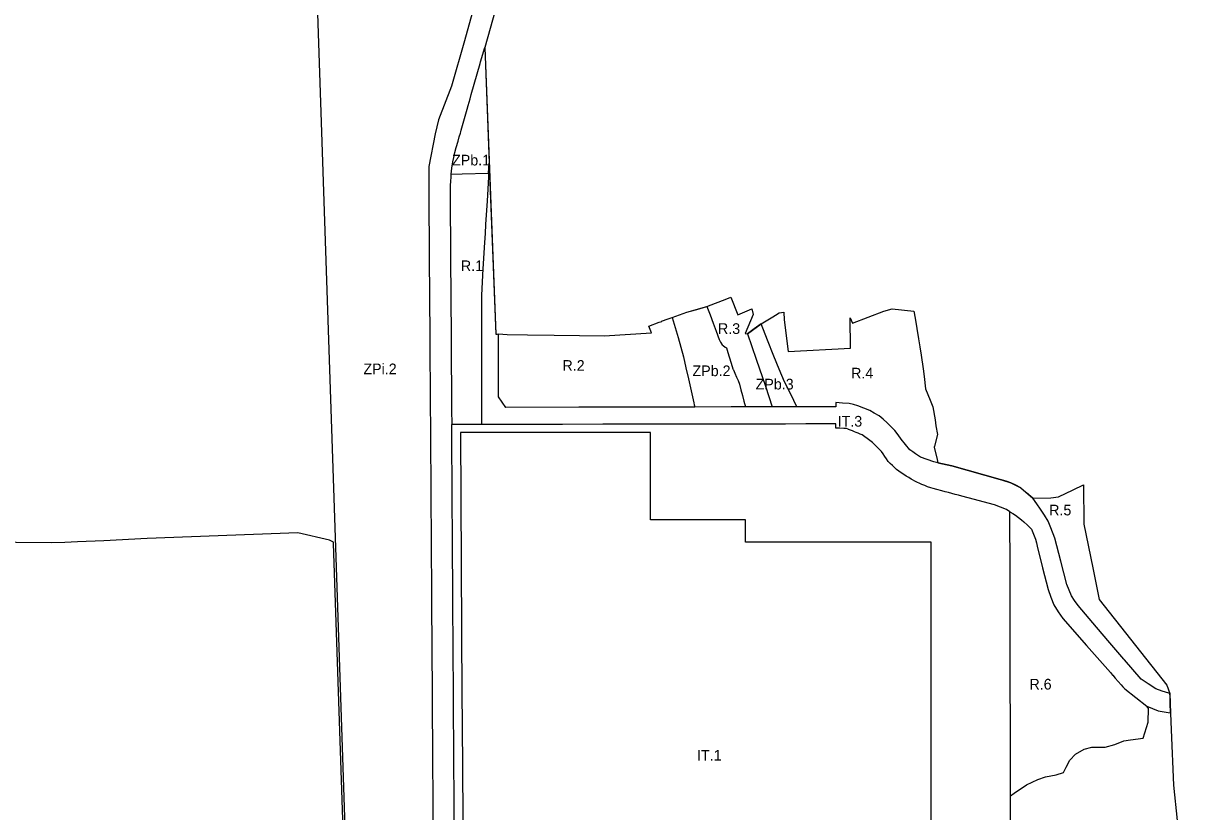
# Model space of a CAD drawing. Extents: x 7434685 to 7436459, y 5545868 to 5548111.
# Drawn here: x 7435281 to 7436385, y 5546598 to 5547337 of the extents above; entities that cross this region are included whole.
import ezdxf

# ---------------------------------------------------------------- set-up
doc = ezdxf.new("R2010")
doc.units = 0
for name, color, linetype in [('LIN_Granica Planu', 7, 'Continuous'), ('LIN_linia regulacyjna_1', 7, 'Continuous'), ('LIN_Linia Zabudowy Nieprzekraczalna', 7, 'Continuous'), ('LIN_Linie Rozgraniczajace', 7, 'Continuous'), ('TXT_Oznaczenia Przeznaczenia', 7, 'Continuous')]:
    doc.layers.add(name, color=color, linetype=linetype)

msp = doc.modelspace()

# ---------------------------------------------------------------- linework, layer by layer
at = {"layer": 'LIN_Granica Planu'}
msp.add_lwpolyline([(7435723.5, 5547350.6), (7435713.4, 5547315), (7435724, 5547046), (7435726.3, 5547046.4), (7435734.4, 5547045.9), (7435753.7, 5547045.4), (7435778.6, 5547045.2), (7435802.4, 5547044.8), (7435825.5, 5547044.4), (7435869.8, 5547047.2), (7435867.2, 5547053.5), (7435876.9, 5547057.4), (7435879.4, 5547058), (7435879.2, 5547058.3), (7435885.4, 5547060.4), (7435889.1, 5547061.8), (7435902.9, 5547066.6), (7435921.8, 5547071.9), (7435940.4, 5547079.3), (7435944.1, 5547080.8), (7435950.8, 5547064.1), (7435963.9, 5547069.8), (7435965.1, 5547064.5), (7435957.5, 5547046.7), (7435959.7, 5547046.3), (7435972.7, 5547055.9), (7435983.5, 5547062.4), (7435986.2, 5547064), (7435989.6, 5547066), (7435993.9, 5547066.8), (7435994.3, 5547059.6), (7435998, 5547029.9), (7436056.4, 5547032.9), (7436055.9, 5547061.5), (7436058.1, 5547056.3), (7436087.6, 5547067.6), (7436095.4, 5547069.9), (7436115.6, 5547067.7), (7436117, 5547061.2), (7436120.1, 5547041.6), (7436121.3, 5547034.2), (7436122.5, 5547026.3), (7436124.4, 5547013.6), (7436125.3, 5547006.3), (7436126.8, 5546994.7), (7436131, 5546984.1), (7436133.6, 5546977.8), (7436135.8, 5546965.8), (7436136.3, 5546960.2), (7436138, 5546952.1), (7436135.1, 5546941), (7436134.9, 5546940.2), (7436137.6, 5546928.4), (7436138.1, 5546925.5), (7436151.5, 5546922.6), (7436196.6, 5546909.9), (7436198, 5546909.5), (7436206.7, 5546906.7), (7436215.9, 5546902), (7436227.2, 5546892.3), (7436244.1, 5546892.7), (7436251.4, 5546893.4), (7436265.1, 5546900.2), (7436274.7, 5546904.8), (7436275.1, 5546867.9), (7436283.5, 5546826.8), (7436289.6, 5546797.3), (7436352.9, 5546717), (7436355.8, 5546709.1), (7436356.5, 5546690.7), (7436357.1, 5546675), (7436359.2, 5546623), (7436366, 5546556.9)], dxfattribs=at)
at = {"layer": 'LIN_linia regulacyjna_1'}
msp.add_lwpolyline([(7435243.6, 5546543.7), (7435297.9, 5546410.5), (7435304.7, 5546395.2), (7435312.3, 5546376.8), (7435316.9, 5546368.8), (7435318.9, 5546363), (7435321.5, 5546284.9), (7435321.5, 5546278.2), (7435590.7, 5546285.6), (7435571.7, 5546849.8), (7435571.7, 5546850.9), (7435567.9, 5546853), (7435538.3, 5546859.6), (7435397.1, 5546854.4), (7435356.3, 5546852.2), (7435331.6, 5546851.4), (7435319.9, 5546850.7), (7435306.9, 5546850.4), (7435208.7, 5546851.2)], dxfattribs=at)
at = {"layer": 'LIN_Linia Zabudowy Nieprzekraczalna'}
for p, q in [((7435868.8, 5546953.9), (7435766.5, 5546953.9)), ((7435868.8, 5546872.1), (7435868.8, 5546953.9)), ((7435914, 5546872.1), (7435868.8, 5546872.1))]:
    msp.add_line(p, q, dxfattribs=at)
for points in [[(7435766.5, 5546953.9), (7435690.6, 5546953.9), (7435692.1, 5546706.5), (7435692.3, 5546682.4), (7435692.6, 5546636), (7435692.7, 5546624), (7435692.8, 5546608.2), (7435693.9, 5546441.6), (7435693.9, 5546431.1), (7435693.9, 5546431.1), (7435694, 5546410.7), (7435694.2, 5546381.2), (7435694.9, 5546359.7), (7435695.6, 5546346.7), (7435695.4, 5546331.7), (7435695.7, 5546310.3), (7435684.1, 5546291.7), (7435651.3, 5546239), (7435648.5, 5546234.6), (7435646.4, 5546231.2), (7435623.7, 5546194.8)], [(7436132, 5546524.1), (7436132, 5546850.9), (7435957.9, 5546850.9), (7435957.9, 5546872.1), (7435914, 5546872.1)]]:
    msp.add_lwpolyline(points, dxfattribs=at)
at = {"layer": 'LIN_Linie Rozgraniczajace'}
msp.add_line((7435717.1, 5547197.1), (7435717.6, 5547206.5), dxfattribs=at)
for points in [[(7435729.9, 5547939.7), (7435729.9, 5547939.7), (7435729.9, 5547939.7), (7435732.1, 5547940.1), (7435745.6, 5547942.7), (7435761.3, 5547945.8), (7435757.5, 5547889.9), (7435754.2, 5547842.4), (7435754, 5547839.8), (7435745.7, 5547707.4), (7435745, 5547694.9), (7435742, 5547643), (7435737.4, 5547559.5), (7435734.9, 5547515.1), (7435730.9, 5547445.3), (7435730.9, 5547444.1), (7435730.9, 5547444.1), (7435730.9, 5547444.1), (7435730, 5547427.8), (7435726.4, 5547363.7), (7435726.2, 5547360), (7435723.5, 5547350.6), (7435713.4, 5547315)], [(7435592.7, 5546283.7), (7435573.9, 5546846), (7435555.2, 5547402.9)], [(7435701.8, 5547347.2), (7435694.4, 5547321.2), (7435682.3, 5547278.7), (7435670.2, 5547247), (7435667, 5547234.1), (7435660.9, 5547203.2), (7435661.1, 5547183.7), (7435661.2, 5547163.3), (7435661.2, 5547156.8), (7435661.2, 5547154.9), (7435661.3, 5547140.3), (7435661.4, 5547137.1), (7435661.4, 5547128.2), (7435661.5, 5547109.1), (7435661.7, 5547090.1), (7435661.8, 5547075.9), (7435661.8, 5547065.2), (7435661.9, 5547059.9), (7435661.9, 5547052.8), (7435661.9, 5547047.2), (7435662.1, 5547028.8), (7435662.1, 5547021.4), (7435662.2, 5547000.2), (7435662.4, 5546979.8), (7435662.4, 5546972.5), (7435662.5, 5546965.1), (7435662.6, 5546961.8), (7435662.6, 5546950.8), (7435662.7, 5546928.1), (7435662.8, 5546920), (7435662.8, 5546908.9), (7435662.9, 5546894.1), (7435663, 5546883.1), (7435663, 5546877), (7435663.1, 5546869.4), (7435663.2, 5546852.1), (7435663.2, 5546849.3), (7435663.2, 5546845.9), (7435663.3, 5546829.3), (7435663.4, 5546823.3), (7435663.4, 5546816.3), (7435663.4, 5546815.3), (7435663.5, 5546808.7), (7435663.5, 5546807.7), (7435663.6, 5546792.3), (7435663.7, 5546779.4), (7435663.8, 5546766.7), (7435663.9, 5546753.1), (7435663.9, 5546740.6), (7435664.1, 5546719.6), (7435664.1, 5546712.7), (7435664.1, 5546706.9), (7435664.2, 5546699.7), (7435664.2, 5546694.6), (7435664.2, 5546692.1), (7435664.2, 5546691.1), (7435664.3, 5546682.8), (7435664.4, 5546668.8), (7435664.5, 5546658.8), (7435664.5, 5546648.7), (7435664.6, 5546636.4), (7435664.6, 5546632.6), (7435664.7, 5546624.4), (7435664.8, 5546608.6), (7435665, 5546569.7)], [(7435681.9, 5547196), (7435682.6, 5547201.8), (7435683.6, 5547207.6), (7435684.4, 5547211.7), (7435685.4, 5547216.3), (7435686.8, 5547221.2), (7435688.5, 5547227.2), (7435689.6, 5547231.1), (7435690.6, 5547234.7), (7435690.9, 5547235.7), (7435691.4, 5547237.5), (7435697, 5547257.1), (7435697.9, 5547260.4), (7435697.9, 5547260.4), (7435699.7, 5547266.8), (7435700.8, 5547270.8), (7435709.2, 5547300), (7435709.6, 5547301.5), (7435709.6, 5547301.5), (7435713.4, 5547315)], [(7435713.4, 5547315), (7435716.3, 5547240), (7435717.6, 5547206.5)], [(7435717.6, 5547206.5), (7435718, 5547197.1), (7435718.7, 5547180.5), (7435724, 5547046), (7435725.1, 5547046.2), (7435726.3, 5547046.4)], [(7435681.9, 5547196), (7435681.8, 5547195.4), (7435681.6, 5547193), (7435681.4, 5547189.8), (7435681, 5547185.3), (7435681.1, 5547182.2), (7435681.1, 5547179.3), (7435681.2, 5547162.8), (7435681.2, 5547156.3), (7435681.2, 5547154.4), (7435681.3, 5547139.9), (7435681.4, 5547136.7), (7435681.4, 5547136.7), (7435681.4, 5547127.8), (7435681.5, 5547108.7), (7435681.7, 5547089.6), (7435681.7, 5547075.4), (7435681.8, 5547064.7), (7435681.9, 5547059.4), (7435681.9, 5547052.3), (7435681.9, 5547046.7), (7435682.1, 5547028.3), (7435682.1, 5547022.3), (7435682.1, 5547021), (7435682.1, 5547015.8), (7435682.2, 5546999.7), (7435682.4, 5546979.3), (7435682.4, 5546972), (7435682.5, 5546964.6), (7435682.5, 5546963.6), (7435682.6, 5546961.3)], [(7435681.9, 5547196), (7435692.2, 5547196.3), (7435717.1, 5547197.1)], [(7435717.1, 5547197.1), (7435717, 5547195.1), (7435716.9, 5547193.4), (7435715.6, 5547171.1), (7435714.3, 5547148.8), (7435713.8, 5547140.5), (7435713.3, 5547132.1), (7435711.8, 5547107.4), (7435710.4, 5547082.7), (7435710.4, 5547063.8), (7435710.4, 5547055), (7435710.3, 5547046.2), (7435710.3, 5547033.4), (7435710.3, 5547020.6), (7435710.3, 5547020.6), (7435710.3, 5546993.9), (7435710.3, 5546967.2), (7435710.3, 5546964.3), (7435710.3, 5546963.6), (7435710.3, 5546961.4)], [(7435921.8, 5547071.9), (7435940.4, 5547079.3), (7435944.1, 5547080.8), (7435950.8, 5547064.1), (7435963.9, 5547069.8), (7435965.1, 5547064.5), (7435957.5, 5547046.7), (7435959.7, 5547046.3)], [(7435889.1, 5547061.8), (7435889.1, 5547061.8), (7435889.1, 5547061.8), (7435896, 5547064.2), (7435902.9, 5547066.6), (7435902.9, 5547066.6), (7435912.4, 5547069.3), (7435921.8, 5547071.9)], [(7435921.8, 5547071.9), (7435924.7, 5547064.2), (7435927.5, 5547056.5), (7435930.4, 5547048.8), (7435933.2, 5547041.1), (7435934.6, 5547038.6), (7435936, 5547036.2), (7435937, 5547035.4), (7435939, 5547033.9), (7435940, 5547033.1), (7435941.3, 5547028.9), (7435942.7, 5547024.7), (7435944.5, 5547018.8), (7435946.1, 5547013.5), (7435946.1, 5547013.5), (7435946.4, 5547013), (7435946.6, 5547012.5), (7435947.9, 5547009.4), (7435949.5, 5547005.8), (7435950.9, 5547002.5), (7435952.4, 5546999.1), (7435953.7, 5546993.8), (7435955.1, 5546988.4), (7435956.5, 5546983.1), (7435957.9, 5546977.8)], [(7435972.7, 5547055.9), (7435983.5, 5547062.4), (7435986.2, 5547064), (7435989.6, 5547066), (7435993.9, 5547066.8), (7435993.9, 5547066.8), (7435994.3, 5547059.6), (7435998, 5547029.9), (7436056.4, 5547032.9), (7436055.9, 5547061.5), (7436055.9, 5547061.5), (7436058.1, 5547056.3), (7436087.6, 5547067.6), (7436095.4, 5547069.9), (7436115.6, 5547067.7), (7436117, 5547061.2), (7436120.1, 5547041.6), (7436121.3, 5547034.2), (7436122.5, 5547026.3), (7436124.4, 5547013.6), (7436125.3, 5547006.3), (7436126.8, 5546994.7), (7436131, 5546984.1), (7436131, 5546984.1), (7436133.6, 5546977.8), (7436135.8, 5546965.8), (7436136.3, 5546960.2), (7436138, 5546952.1), (7436135.1, 5546941), (7436134.9, 5546940.2), (7436137.6, 5546928.4), (7436138.1, 5546925.5)], [(7435726.3, 5547046.4), (7435734.4, 5547045.9), (7435753.7, 5547045.4), (7435778.6, 5547045.2), (7435802.4, 5547044.8), (7435825.5, 5547044.4), (7435869.8, 5547047.2), (7435867.2, 5547053.5), (7435876.9, 5547057.4), (7435876.9, 5547057.4), (7435879.4, 5547058), (7435879.4, 5547058), (7435879.2, 5547058.3), (7435885.4, 5547060.4), (7435889.1, 5547061.8), (7435889.1, 5547061.8)], [(7435889.1, 5547061.8), (7435889.1, 5547061.8), (7435889.1, 5547061.8), (7435892, 5547052.3), (7435894.9, 5547042.9), (7435894.9, 5547042.9), (7435897.3, 5547033.9), (7435899.8, 5547024.8), (7435902.1, 5547014.5), (7435904.4, 5547004.2), (7435904.4, 5547004.2), (7435906.9, 5546993), (7435909.4, 5546981.7), (7435909.9, 5546979.7), (7435910.4, 5546977.7)], [(7435972.7, 5547055.9), (7435966.2, 5547051.1), (7435959.7, 5547046.3)], [(7436006.1, 5546977.9), (7436006.1, 5546977.9), (7436006.1, 5546977.9), (7436000.3, 5546989.7), (7435994.5, 5547001.5), (7435989.5, 5547013.4), (7435984.5, 5547025.4), (7435984.5, 5547025.4), (7435978.6, 5547040.6), (7435972.7, 5547055.9)], [(7435910.4, 5546977.7), (7435898.6, 5546977.7), (7435898.6, 5546977.7), (7435897, 5546977.7), (7435873.1, 5546977.6), (7435869.9, 5546977.6), (7435801.6, 5546977.5), (7435733.2, 5546977.4), (7435729.7, 5546982.4), (7435726.3, 5546987.4), (7435726.3, 5546987.4), (7435726.3, 5547020.4), (7435726.3, 5547033.4), (7435726.3, 5547039.9), (7435726.3, 5547046.4)], [(7435959.7, 5547046.3), (7435968, 5547022.7), (7435976.7, 5546997.2), (7435982.8, 5546977.8), (7435982.8, 5546977.8), (7435982.8, 5546977.8)], [(7436138.1, 5546925.5), (7436134.5, 5546926.3), (7436128.2, 5546928.4), (7436122, 5546930.6), (7436117.4, 5546933.8), (7436114.8, 5546935.6), (7436112.1, 5546937.5), (7436104, 5546947.7), (7436101, 5546951.7), (7436098, 5546955.7), (7436095.2, 5546958.5), (7436090.7, 5546963), (7436086.9, 5546966.2), (7436083.1, 5546969.4), (7436083.1, 5546969.4), (7436078.7, 5546971.9), (7436074.4, 5546974.5), (7436068.8, 5546976.8), (7436063.1, 5546979), (7436059.1, 5546980), (7436055.1, 5546981), (7436048.8, 5546981.5), (7436042.5, 5546982), (7436042.5, 5546979.9), (7436042.5, 5546977.9), (7436037.5, 5546977.9), (7436032.5, 5546977.9), (7436019.3, 5546977.9), (7436006.1, 5546977.9), (7436006.1, 5546977.9), (7436006.1, 5546977.9)], [(7435957.9, 5546977.8), (7435948.4, 5546977.8), (7435944.5, 5546977.8), (7435910.4, 5546977.7)], [(7435982.8, 5546977.8), (7435970.3, 5546977.8), (7435957.9, 5546977.8)], [(7436006.1, 5546977.9), (7435994.4, 5546977.8), (7435982.8, 5546977.8)], [(7435710.3, 5546961.4), (7435697.9, 5546961.4), (7435682.6, 5546961.3), (7435682.6, 5546961.3)], [(7435685, 5546574.3), (7435684.8, 5546600.8), (7435684.8, 5546608.2), (7435684.7, 5546623.9), (7435684.6, 5546632.2), (7435684.6, 5546635.9), (7435684.5, 5546648.2), (7435684.4, 5546658.4), (7435684.4, 5546668.3), (7435684.3, 5546682.3), (7435684.2, 5546690.4), (7435684.2, 5546690.7), (7435684.2, 5546691.7), (7435684.2, 5546694.1), (7435684.1, 5546706.4), (7435684.1, 5546712.2), (7435684.1, 5546719.1), (7435683.9, 5546740.2), (7435683.8, 5546752.7), (7435683.8, 5546766.2), (7435683.7, 5546778.9), (7435683.6, 5546791.8), (7435683.5, 5546807.4), (7435683.5, 5546808.2), (7435683.4, 5546814.9), (7435683.4, 5546815.8), (7435683.4, 5546822.8), (7435683.3, 5546828.8), (7435683.2, 5546845.5), (7435683.2, 5546848.8), (7435683.2, 5546851.6), (7435683.1, 5546869), (7435683, 5546876.5), (7435683, 5546882.6), (7435682.9, 5546893.6), (7435682.8, 5546908.5), (7435682.8, 5546919.5), (7435682.7, 5546927.6), (7435682.7, 5546935.9), (7435682.6, 5546941.8), (7435682.6, 5546950.4), (7435682.6, 5546953.6), (7435682.6, 5546961.3), (7435682.6, 5546961.3)], [(7436205.8, 5546879.4), (7436202.5, 5546881.5), (7436196.9, 5546883.7), (7436191.4, 5546885.9), (7436166.8, 5546892.5), (7436160.6, 5546894.2), (7436157.5, 5546895), (7436154.5, 5546895.8), (7436151.4, 5546896.7), (7436148.3, 5546897.5), (7436145.2, 5546898.3), (7436142.1, 5546899.2), (7436137.3, 5546900.4), (7436136.2, 5546900.7), (7436135.1, 5546901), (7436134, 5546901.3), (7436131.8, 5546901.9), (7436128.5, 5546902.8), (7436128.5, 5546902.8), (7436125.9, 5546904), (7436123.2, 5546905.1), (7436121.9, 5546905.7), (7436117.8, 5546907.5), (7436113.2, 5546910.2), (7436111, 5546911.5), (7436108.5, 5546913), (7436106.3, 5546914.6), (7436104, 5546916.1), (7436101.8, 5546917.7), (7436099.6, 5546919.2), (7436099.6, 5546919.2), (7436097.6, 5546921.1), (7436095.7, 5546922.9), (7436093.7, 5546924.8), (7436091.7, 5546926.7), (7436090.2, 5546929), (7436088.6, 5546931.3), (7436087, 5546933.7), (7436085.5, 5546936), (7436083.3, 5546938.2), (7436080.2, 5546941.4), (7436077, 5546944.6), (7436072.1, 5546948.1), (7436069.7, 5546949.9), (7436067.3, 5546951.7), (7436065.4, 5546952.4), (7436063.6, 5546953.1), (7436061.8, 5546953.8), (7436060, 5546954.6), (7436058.2, 5546955.3), (7436056.4, 5546956), (7436054.6, 5546956.8), (7436054.2, 5546956.9), (7436052.7, 5546957.5), (7436050.2, 5546957.6), (7436046.4, 5546957.8), (7436044.5, 5546957.9), (7436042.5, 5546958), (7436042.5, 5546960), (7436042.5, 5546961.9), (7436035.5, 5546961.9), (7436032.5, 5546961.9), (7436028.4, 5546961.9), (7436021.4, 5546961.9), (7436014.4, 5546961.9), (7435995.4, 5546961.8), (7435988.1, 5546961.8), (7435976.4, 5546961.8), (7435961.8, 5546961.8), (7435957.3, 5546961.8), (7435953.3, 5546961.8), (7435945.2, 5546961.8), (7435938.3, 5546961.7), (7435932.4, 5546961.7), (7435919.6, 5546961.7), (7435916.4, 5546961.7), (7435909.2, 5546961.7), (7435900.3, 5546961.7), (7435897.2, 5546961.7), (7435881.3, 5546961.7), (7435874.9, 5546961.6), (7435870.4, 5546961.6), (7435868.8, 5546961.6), (7435862.3, 5546961.6), (7435824.3, 5546961.6), (7435786.3, 5546961.5), (7435748.3, 5546961.4), (7435710.3, 5546961.4)], [(7436227.2, 5546892.3), (7436221.5, 5546897.2), (7436215.9, 5546902), (7436211.3, 5546904.4), (7436206.7, 5546906.7), (7436202.3, 5546908.1), (7436198, 5546909.5), (7436196.6, 5546909.9), (7436151.5, 5546922.6), (7436151.5, 5546922.6), (7436138.1, 5546925.5)], [(7436227.2, 5546892.3), (7436244.1, 5546892.7), (7436251.4, 5546893.4), (7436265.1, 5546900.2), (7436274.7, 5546904.8), (7436275.1, 5546867.9), (7436283.5, 5546826.8), (7436289.6, 5546797.3), (7436352.9, 5546717), (7436355.8, 5546709.1)], [(7436355.8, 5546709.1), (7436354.7, 5546709.4), (7436348.7, 5546711.3), (7436342.6, 5546713.3), (7436335.3, 5546718.1), (7436335.3, 5546718.1), (7436328.8, 5546722.4), (7436313.2, 5546740.7), (7436312.6, 5546741.4), (7436297.7, 5546758.9), (7436283.7, 5546775.3), (7436269.7, 5546791.7), (7436266.5, 5546796.2), (7436263.4, 5546800.8), (7436263.4, 5546800.8), (7436261.3, 5546806.1), (7436259.2, 5546811.4), (7436253.5, 5546833.1), (7436247.8, 5546854.8), (7436244.3, 5546864.4), (7436241.6, 5546870.6), (7436241.6, 5546870.6), (7436238.1, 5546876.3), (7436234.6, 5546882), (7436230.9, 5546887.1), (7436227.2, 5546892.3)], [(7436206.5, 5546613.2), (7436206.3, 5546673.8), (7436206.2, 5546725.2), (7436206.1, 5546776.6), (7436206, 5546802.7), (7436205.9, 5546828), (7436205.9, 5546841.1), (7436205.8, 5546860.2), (7436205.8, 5546878.1), (7436205.8, 5546879.4)], [(7436205.8, 5546879.4), (7436208.4, 5546877.8), (7436211, 5546876.2), (7436213.9, 5546874), (7436216.8, 5546871.8), (7436218.8, 5546870.2), (7436222.4, 5546866.8), (7436225.9, 5546863.3), (7436227.8, 5546858.5), (7436229.8, 5546853.7), (7436230.6, 5546850.5), (7436231.4, 5546847.3), (7436231.4, 5546847.3), (7436236.5, 5546827), (7436241.7, 5546806.7), (7436244.3, 5546799.4), (7436246.9, 5546792.1), (7436251.2, 5546785.8), (7436255.4, 5546779.5), (7436277.7, 5546754.1), (7436300, 5546728.7), (7436302, 5546726.4), (7436302.2, 5546726.2), (7436304.4, 5546723.6), (7436307.3, 5546720.4), (7436310.2, 5546717.1), (7436311.8, 5546715.2), (7436313.5, 5546713.3), (7436323.9, 5546705.3), (7436334.3, 5546697.2)], [(7436356.5, 5546690.7), (7436356.1, 5546699.9), (7436355.9, 5546706.2), (7436355.8, 5546709.1)], [(7436206.5, 5546613.2), (7436209.9, 5546615.7), (7436221.4, 5546623.3), (7436232.1, 5546628.5), (7436239.1, 5546630.9), (7436249.2, 5546632.9), (7436256.1, 5546634.9), (7436258.6, 5546640), (7436262.1, 5546646.6), (7436267.3, 5546652.1), (7436275.4, 5546657), (7436282.7, 5546658.7), (7436295.2, 5546658.8), (7436304.3, 5546661.4), (7436312.7, 5546664.8), (7436318.8, 5546665.5), (7436330.7, 5546667.2), (7436335.4, 5546682.2), (7436335.7, 5546695), (7436334.3, 5546697.2)], [(7436334.3, 5546697.2), (7436339.5, 5546695), (7436344.7, 5546692.9), (7436350.3, 5546691.8), (7436356, 5546690.8), (7436356.5, 5546690.7)], [(7436356.5, 5546690.7), (7436356.8, 5546682.9), (7436357.1, 5546675), (7436359.2, 5546623), (7436366, 5546556.9), (7436385.4, 5546486.1)], [(7436206.9, 5546459.9), (7436206.9, 5546468.1), (7436206.9, 5546471.8), (7436206.9, 5546471.8), (7436206.8, 5546477.2), (7436206.8, 5546481.7), (7436206.8, 5546486.2), (7436206.5, 5546613.2)]]:
    msp.add_lwpolyline(points, dxfattribs=at)

# ---------------------------------------------------------------- texts
at = {"layer": 'TXT_Oznaczenia Przeznaczenia'}
for s, p in [('ZPb.1', (7435682.8, 5547204.3)), ('R.1', (7435691.1, 5547105.2)), ('R.3', (7435932.1, 5547046.3)), ('ZPi.2', (7435599.7, 5547008.5)), ('R.2', (7435786.3, 5547011.7)), ('ZPb.2', (7435908.2, 5547006.7)), ('R.4', (7436056.9, 5547004.5)), ('ZPb.3', (7435967.4, 5546994.2)), ('IT.3', (7436044.3, 5546959.4)), ('R.5', (7436242.6, 5546876.1)), ('R.6', (7436224.1, 5546712.8)), ('IT.1', (7435912.5, 5546646.1))]:
    msp.add_text(s, height=10, dxfattribs=at).set_placement(p)

doc.saveas('drawing.dxf')
